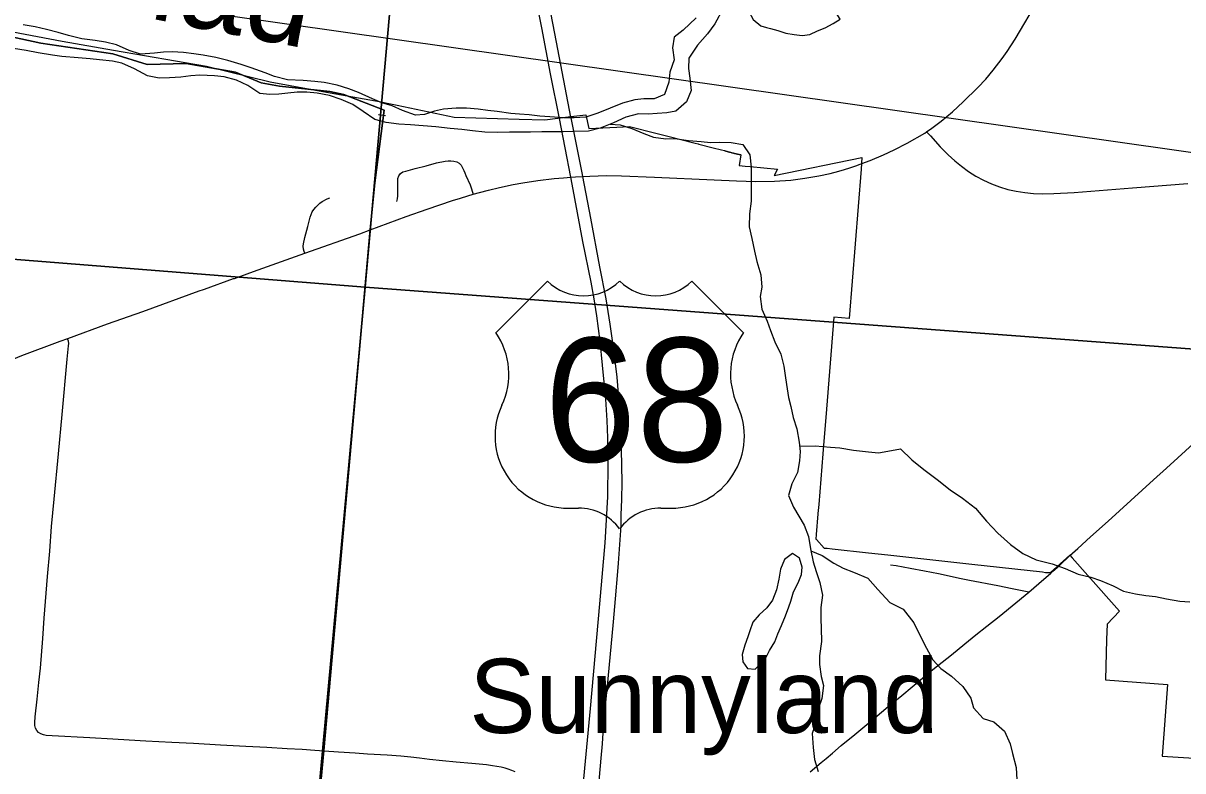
# Model space of a CAD drawing. Extents: x 0 to 34, y 0 to 22.
# Drawn here: x 6.536 to 7.77, y 18.205 to 19.001 of the extents above; entities that cross this region are included whole.
import ezdxf

# ---------------------------------------------------------------- set-up
doc = ezdxf.new("R2010")
doc.units = 0
for name, color, linetype in [('GM_X_Corporation', 7, 'Continuous'), ('GM_X_County_Road', 7, 'Continuous'), ('GM_X_Major_River', 7, 'Continuous'), ('GM_X_Major_River_Text', 7, 'Continuous'), ('GM_X_Minor_Lake', 7, 'Continuous'), ('GM_X_Minor_River', 7, 'Continuous'), ('GM_X_Township_Road', 7, 'Continuous'), ('GM_X_Unincorporated_Text', 7, 'Continuous'), ('GM_X_US_Location', 7, 'Continuous'), ('GM_X_US_Route', 7, 'Continuous'), ('GM_X_US_Shield', 7, 'Continuous'), ('SH_Text', 7, 'Continuous')]:
    doc.layers.add(name, color=color, linetype=linetype)

msp = doc.modelspace()

# ---------------------------------------------------------------- linework, layer by layer
at = {"layer": 'GM_X_Corporation'}
for points in [[(5.9917, 19.818), (6.9896, 19.7221), (6.9001, 18.7194), (5.8857, 18.8)], [(6.9896, 19.7221), (8.0005, 19.6268), (7.9102, 18.6438), (6.9001, 18.7194)], [(5.8857, 18.8), (6.9001, 18.7194), (6.8066, 17.7025), (5.8048, 17.783)]]:
    msp.add_lwpolyline(points, close=True, dxfattribs=at)
for points in [[(6.8137, 17.7739), (6.8245, 17.8909), (6.8563, 18.2261), (6.9053, 18.781), (6.9106, 18.8306), (6.9204, 18.908), (6.8775, 18.9245), (6.8626, 18.9279), (6.8089, 18.9336), (6.7895, 18.937), (6.762, 18.9484), (6.7095, 18.9576), (6.6683, 18.9564), (6.6317, 18.9678), (6.5552, 18.9793), (6.4809, 18.9953)], [(6.4809, 18.9953), (6.5552, 18.9793), (6.6317, 18.9678), (6.6683, 18.9564), (6.7095, 18.9576), (6.762, 18.9484), (6.7895, 18.937), (6.8089, 18.9336), (6.8626, 18.9279), (6.8775, 18.9245), (6.9204, 18.908), (6.9106, 18.8306), (6.9053, 18.781), (6.8563, 18.2261), (6.8245, 17.8909), (6.8137, 17.7739)], [(6.5121, 18.9937), (6.5779, 18.9815), (6.6325, 18.9717), (6.7314, 18.9547), (6.7991, 18.9381), (6.8628, 18.9265), (6.9171, 18.9167), (6.9219, 18.9157), (6.9342, 18.9131), (6.9948, 18.9004), (7.0641, 18.8984), (7.0913, 18.8976), (7.1189, 18.9011), (7.1351, 18.9031), (7.138, 18.8882), (7.1678, 18.8898), (7.1815, 18.8905), (7.2093, 18.8834), (7.2222, 18.8801), (7.2514, 18.8727), (7.2543, 18.872), (7.255, 18.8718), (7.2703, 18.8679), (7.2792, 18.8657), (7.2824, 18.8648), (7.2826, 18.8648), (7.2827, 18.8647), (7.2829, 18.8647), (7.2831, 18.8646), (7.2832, 18.8646), (7.2834, 18.8645), (7.2836, 18.8645), (7.2838, 18.8644), (7.2839, 18.8644), (7.2841, 18.8643), (7.2843, 18.8643), (7.2844, 18.8642), (7.2846, 18.8642), (7.2848, 18.8642), (7.2849, 18.8641), (7.2851, 18.8641), (7.2853, 18.864), (7.2855, 18.864), (7.2856, 18.8639), (7.2858, 18.8639), (7.286, 18.8638), (7.2861, 18.8638), (7.2863, 18.8637), (7.2865, 18.8637), (7.2866, 18.8636), (7.2868, 18.8636), (7.287, 18.8635), (7.2872, 18.8635), (7.2873, 18.8634), (7.2875, 18.8634), (7.2877, 18.8634), (7.2878, 18.8633), (7.288, 18.8633), (7.2881, 18.8632), (7.2882, 18.8632), (7.2884, 18.8632), (7.2885, 18.8631), (7.2887, 18.8631), (7.2889, 18.863), (7.289, 18.863), (7.2894, 18.8629), (7.2895, 18.8629), (7.2897, 18.8628), (7.2899, 18.8628), (7.2901, 18.8627), (7.2902, 18.8627), (7.2904, 18.8626), (7.2906, 18.8626), (7.2907, 18.8626), (7.2909, 18.8625), (7.2911, 18.8625), (7.2913, 18.8624), (7.2914, 18.8624), (7.2916, 18.8623), (7.2918, 18.8623), (7.2919, 18.8623), (7.2921, 18.8622), (7.2923, 18.8622), (7.2925, 18.8621), (7.2926, 18.8621), (7.2928, 18.862), (7.293, 18.862), (7.2932, 18.862), (7.2933, 18.8619), (7.2935, 18.8619), (7.2937, 18.8618), (7.2938, 18.8618), (7.2939, 18.8618), (7.294, 18.8618), (7.2942, 18.8617), (7.2944, 18.8617), (7.2945, 18.8616), (7.2947, 18.8616), (7.2949, 18.8616), (7.295, 18.8615), (7.2952, 18.8615), (7.2954, 18.8614), (7.2956, 18.8614), (7.2957, 18.8614), (7.2959, 18.8613), (7.2961, 18.8613), (7.2963, 18.8613), (7.2964, 18.8612), (7.2966, 18.8612), (7.2968, 18.8611), (7.2969, 18.8611), (7.2971, 18.8611), (7.2973, 18.861), (7.2975, 18.861), (7.2976, 18.861), (7.2978, 18.8609), (7.298, 18.8609), (7.2982, 18.8608), (7.2983, 18.8608), (7.2985, 18.8608), (7.2987, 18.8607), (7.2988, 18.8607), (7.299, 18.8607), (7.2992, 18.8606), (7.2994, 18.8606), (7.2995, 18.8606), (7.2997, 18.8605), (7.2982, 18.849), (7.3044, 18.8484), (7.3098, 18.8479), (7.3388, 18.8451), (7.3388, 18.8451), (7.3354, 18.8385), (7.4287, 18.8574), (7.4278, 18.845), (7.4153, 18.686), (7.3989, 18.6874), (7.3902, 18.5808), (7.3882, 18.5555), (7.3827, 18.488), (7.3819, 18.4785), (7.3819, 18.4783), (7.3801, 18.4563), (7.3797, 18.4513), (7.3802, 18.4507), (7.3887, 18.4417), (7.3919, 18.4414), (7.3971, 18.4408), (7.4356, 18.4366), (7.4564, 18.4343), (7.5264, 18.4266), (7.5457, 18.4244), (7.6209, 18.4162), (7.6241, 18.4158), (7.6294, 18.4155), (7.6499, 18.4342), (7.6524, 18.4314), (7.6691, 18.4125), (7.7027, 18.3745), (7.6896, 18.3605), (7.6891, 18.3445), (7.6878, 18.3014), (7.754, 18.2964), (7.748, 18.2201), (7.8666, 18.2127)], [(6.8132, 17.7739), (6.9001, 18.7194), (7.9102, 18.6438), (7.8167, 17.7739)]]:
    msp.add_lwpolyline(points, dxfattribs=at)
at = {"layer": 'GM_X_County_Road'}
for points in [[(7.4975, 18.8849), (7.5032, 18.8887), (7.5131, 18.8963), (7.525, 18.9062), (7.5365, 18.9167), (7.552, 18.9319), (7.5605, 18.941), (7.5685, 18.9505), (7.578, 18.9628), (7.5833, 18.9704), (7.5916, 18.9836), (7.6169, 19.0265)], [(7.4267, 18.8504), (7.4285, 18.851), (7.4374, 18.8543), (7.4517, 18.8603), (7.4629, 18.8655), (7.4767, 18.8728), (7.4956, 18.8835), (7.4975, 18.8849)], [(7.4975, 18.8849), (7.5015, 18.8805), (7.5119, 18.869), (7.5206, 18.8602), (7.5275, 18.8539), (7.5346, 18.8481), (7.5421, 18.8427), (7.5499, 18.8377), (7.5581, 18.8333), (7.5665, 18.8295), (7.5751, 18.8262), (7.584, 18.8235), (7.593, 18.8215), (7.6021, 18.8201), (7.6113, 18.8193), (7.6206, 18.8189), (7.633, 18.8191), (7.6546, 18.8204), (7.7166, 18.8252), (7.7755, 18.8298)], [(7.111, 18.8359), (7.1189, 18.8365), (7.1238, 18.8369), (7.1317, 18.8373), (7.1393, 18.8377), (7.1568, 18.8384), (7.173, 18.8381), (7.2081, 18.8366), (7.2716, 18.8336), (7.2951, 18.8325), (7.3157, 18.8319), (7.3358, 18.8322), (7.3529, 18.8334), (7.3679, 18.8354), (7.3829, 18.8379), (7.3948, 18.8405), (7.4043, 18.843), (7.4101, 18.8447), (7.4159, 18.8466), (7.4223, 18.8488), (7.4267, 18.8504)], [(7.0151, 18.8185), (7.0217, 18.8203), (7.0314, 18.8228), (7.043, 18.8256), (7.0577, 18.8287), (7.0679, 18.8304), (7.0839, 18.833), (7.1011, 18.8351), (7.111, 18.8359)], [(6.9055, 18.7805), (6.9439, 18.7947), (6.9661, 18.8024), (6.993, 18.8116), (7.0014, 18.8143), (7.0094, 18.8167), (7.0151, 18.8185)], [(6.8358, 18.7555), (6.8943, 18.7763), (6.9055, 18.7805)], [(6.7601, 18.7285), (6.7611, 18.7288), (6.7814, 18.7361), (6.8358, 18.7555)], [(6.7282, 18.7171), (6.7291, 18.7174), (6.7601, 18.7285)], [(6.5836, 18.6647), (6.6261, 18.6803), (6.6635, 18.6935), (6.7236, 18.7154), (6.7282, 18.7171)], [(6.2717, 18.5103), (6.3025, 18.5272), (6.3488, 18.5524), (6.3883, 18.5739), (6.4201, 18.591), (6.4474, 18.6058), (6.4777, 18.6217), (6.4917, 18.6285), (6.5117, 18.6372), (6.5348, 18.6466), (6.5755, 18.6618), (6.5836, 18.6647)], [(7.6319, 18.417), (7.6389, 18.4231), (7.6501, 18.4337), (7.6583, 18.4412), (7.672, 18.4538), (7.6906, 18.4704), (7.7388, 18.5142), (7.7527, 18.5267), (7.785, 18.5561), (7.8029, 18.5733), (7.821, 18.5904), (7.8357, 18.6041)], [(7.6063, 18.3948), (7.6168, 18.4039), (7.6296, 18.415), (7.6319, 18.417)], [(7.3906, 18.2178), (7.3973, 18.2234), (7.4067, 18.2314), (7.421, 18.2433), (7.4425, 18.261), (7.4568, 18.2729), (7.4712, 18.2847), (7.5042, 18.3123), (7.524, 18.3281), (7.5383, 18.3398), (7.5499, 18.3492), (7.5615, 18.3584), (7.5746, 18.3689), (7.6063, 18.3948)], [(7.3737, 18.2034), (7.3855, 18.2134), (7.3906, 18.2178)]]:
    msp.add_lwpolyline(points, dxfattribs=at)
at = {"layer": 'GM_X_Major_River'}
for points in [[(7.2809, 19.0162), (7.2721, 18.9997), (7.2643, 18.9893), (7.2538, 18.977), (7.2447, 18.9632), (7.2441, 18.9522), (7.2457, 18.9419), (7.2469, 18.9289), (7.2421, 18.9169), (7.2308, 18.9069), (7.2213, 18.9052), (7.211, 18.9043), (7.2012, 18.9038), (7.1909, 18.904), (7.1776, 18.9006), (7.1645, 18.8944), (7.1503, 18.8887), (7.1377, 18.8856), (7.121, 18.8852), (7.1108, 18.885), (7.0982, 18.885), (7.088, 18.8848), (7.0762, 18.8843), (7.0667, 18.8846), (7.0538, 18.8845), (7.0405, 18.884), (7.0273, 18.8844), (7.0144, 18.8858), (7.003, 18.8872), (6.9905, 18.8883), (6.9754, 18.8901), (6.9618, 18.8912), (6.9485, 18.8923), (6.936, 18.893), (6.9224, 18.8948), (6.9103, 18.8981), (6.898, 18.9064), (6.8871, 18.9138), (6.8747, 18.9194), (6.8623, 18.9235), (6.8491, 18.9261), (6.8381, 18.9271), (6.8279, 18.927), (6.818, 18.9261), (6.8081, 18.9248)], [(7.2522, 19.0063), (7.2386, 18.9929), (7.2289, 18.9856), (7.2271, 18.9742), (7.2291, 18.9616), (7.2242, 18.9484), (7.2232, 18.9378), (7.2187, 18.9247), (7.2076, 18.92), (7.1966, 18.9199), (7.1871, 18.9189), (7.1741, 18.9155), (7.1607, 18.9101), (7.1477, 18.9047), (7.135, 18.9004), (7.1225, 18.8996), (7.1115, 18.8998), (7.0967, 18.9009), (7.0861, 18.9016)], [(7.0861, 18.9016), (7.0748, 18.903), (7.0645, 18.9036), (7.0551, 18.9042), (7.0407, 18.9064), (7.0305, 18.9074), (7.0202, 18.9088), (7.0081, 18.9099), (6.9971, 18.9101), (6.9834, 18.9089), (6.9739, 18.9069), (6.9632, 18.9033), (6.9537, 18.9024), (6.9398, 18.9077), (6.9289, 18.9125), (6.9179, 18.9158), (6.9078, 18.9198), (6.8931, 18.9266), (6.8826, 18.9307), (6.8702, 18.9344), (6.8566, 18.9373), (6.8467, 18.9383), (6.8342, 18.9394), (6.8176, 18.9402), (6.8036, 18.9439), (6.7938, 18.9476), (6.7788, 18.9528), (6.7682, 18.9565), (6.7539, 18.9606), (6.7411, 18.964), (6.7278, 18.9666), (6.718, 18.9679), (6.7067, 18.9693), (6.6949, 18.97), (6.6854, 18.9698), (6.6759, 18.9686), (6.6611, 18.9674), (6.649, 18.9715), (6.6355, 18.9775), (6.6238, 18.9804), (6.6128, 18.9822), (6.5985, 18.984), (6.5845, 18.9874), (6.5736, 18.9907), (6.5611, 18.9937), (6.549, 18.9966), (6.5362, 18.9988)], [(6.8081, 18.9248), (6.7986, 18.9247), (6.788, 18.9257), (6.7753, 18.9343), (6.7633, 18.9399), (6.7501, 18.9433), (6.7399, 18.9446), (6.7243, 18.945), (6.7148, 18.9445), (6.7041, 18.9432), (6.692, 18.9424), (6.681, 18.9419), (6.6685, 18.9444), (6.6546, 18.952), (6.6411, 18.958), (6.6313, 18.9601), (6.6173, 18.9616), (6.6074, 18.9626), (6.5946, 18.9636), (6.5775, 18.9652), (6.5673, 18.9665), (6.5522, 18.9688), (6.5393, 18.9714), (6.5261, 18.9736)]]:
    msp.add_lwpolyline(points, dxfattribs=at)
at = {"layer": 'GM_X_Minor_Lake'}
for points in [[(7.3619, 19.0777), (7.3527, 19.0713), (7.3443, 19.0631), (7.3367, 19.0548), (7.3276, 19.0465), (7.3199, 19.0382), (7.3135, 19.0307), (7.3066, 19.022), (7.3084, 19.0129), (7.3129, 19.0045), (7.3211, 18.9976), (7.3271, 18.996)], [(7.3271, 18.996), (7.3313, 18.9949), (7.3393, 18.9926), (7.3479, 18.9898), (7.3566, 18.9883), (7.365, 18.9874), (7.3733, 18.9885), (7.3816, 18.9922), (7.3896, 18.9956), (7.398, 19.0001), (7.4056, 19.0046), (7.4007, 19.0126), (7.397, 19.0206), (7.3914, 19.0286), (7.3858, 19.037), (7.3798, 19.045), (7.3742, 19.0541), (7.3701, 19.0625), (7.3648, 19.0709), (7.3619, 19.0777)], [(7.3152, 18.3129), (7.3255, 18.3226), (7.3305, 18.3325), (7.3359, 18.3419), (7.3394, 18.3502), (7.3432, 18.3593), (7.3474, 18.3695), (7.3509, 18.379), (7.3532, 18.385), (7.356, 18.3952), (7.3609, 18.4047), (7.3644, 18.4134), (7.3652, 18.4213), (7.3623, 18.4308), (7.3547, 18.4358), (7.3491, 18.4315)], [(7.3491, 18.4315), (7.3464, 18.4294), (7.3421, 18.4192), (7.3402, 18.4086), (7.3378, 18.3972), (7.3336, 18.3863), (7.3275, 18.378), (7.3195, 18.3705), (7.3126, 18.3629), (7.3095, 18.3535), (7.3072, 18.347), (7.3041, 18.3383), (7.3014, 18.3285), (7.3021, 18.3205), (7.3069, 18.3133), (7.3152, 18.3129)]]:
    msp.add_lwpolyline(points, dxfattribs=at)
at = {"layer": 'GM_X_Minor_River'}
for points in [[(6.9217, 18.902), (6.9148, 18.9031), (6.9144, 18.9031)], [(7.1609, 18.8929), (7.1713, 18.8922), (7.1838, 18.8883), (7.1966, 18.8829), (7.2071, 18.879), (7.22, 18.8774), (7.2298, 18.8777), (7.2442, 18.8757), (7.2578, 18.8745), (7.2676, 18.8736), (7.2775, 18.8739), (7.2896, 18.8735), (7.302, 18.8715), (7.3095, 18.8604), (7.3109, 18.8471), (7.3108, 18.835), (7.3107, 18.8225), (7.311, 18.8111), (7.309, 18.7975), (7.3086, 18.7838), (7.3115, 18.7713), (7.3144, 18.7576), (7.317, 18.7466), (7.321, 18.7326), (7.3221, 18.7193), (7.3205, 18.7094), (7.3223, 18.6961), (7.3279, 18.6832), (7.3316, 18.6733), (7.336, 18.6612), (7.3423, 18.6482), (7.3457, 18.6353), (7.3471, 18.6254), (7.3485, 18.6159), (7.3507, 18.6019), (7.3529, 18.5924), (7.3555, 18.5806), (7.3595, 18.5685), (7.3621, 18.5544), (7.3631, 18.5446), (7.3623, 18.5347), (7.3603, 18.5222), (7.3542, 18.5101), (7.3507, 18.4976), (7.3559, 18.4851), (7.3615, 18.4756), (7.3671, 18.466), (7.3719, 18.4539), (7.3741, 18.441), (7.377, 18.4269), (7.38, 18.4167), (7.384, 18.4049), (7.3866, 18.3916), (7.385, 18.3783), (7.3849, 18.3662), (7.3855, 18.3559), (7.3858, 18.3423), (7.3834, 18.3271), (7.3834, 18.3177), (7.3852, 18.3048), (7.3877, 18.2953), (7.3861, 18.2816), (7.3823, 18.2703), (7.3795, 18.2551), (7.3756, 18.2442), (7.377, 18.2294), (7.3781, 18.2165), (7.3821, 18.2039)], [(7.3625, 18.5502), (7.3791, 18.5505), (7.3953, 18.5492), (7.4051, 18.5484), (7.4199, 18.546), (7.4358, 18.544), (7.4463, 18.5432), (7.46, 18.5457), (7.4698, 18.5472), (7.4818, 18.5357), (7.4946, 18.5254), (7.5089, 18.5147), (7.5225, 18.5036), (7.5356, 18.4948), (7.5496, 18.484), (7.5612, 18.4703), (7.5732, 18.4577), (7.5867, 18.4455), (7.5999, 18.4359), (7.6142, 18.429), (7.6312, 18.425), (7.6448, 18.42), (7.6587, 18.4138), (7.6723, 18.4107), (7.6825, 18.4072), (7.6961, 18.4014), (7.707, 18.3957), (7.7199, 18.3929), (7.7308, 18.3913), (7.741, 18.3901), (7.7527, 18.3877), (7.7671, 18.385), (7.7777, 18.3845)], [(7.3745, 18.4388), (7.3865, 18.4337), (7.3989, 18.4256), (7.4087, 18.4202), (7.4197, 18.416), (7.4351, 18.4098), (7.4456, 18.3976), (7.4584, 18.3838), (7.4727, 18.3765), (7.4839, 18.3621), (7.4899, 18.3495), (7.4974, 18.335), (7.5041, 18.3228), (7.5127, 18.3133), (7.524, 18.3053), (7.536, 18.2942), (7.5446, 18.282), (7.5476, 18.2717), (7.5577, 18.2603), (7.569, 18.2568), (7.5803, 18.2468), (7.5863, 18.2331), (7.5888, 18.2229), (7.5929, 18.2081), (7.5935, 18.1948)]]:
    msp.add_lwpolyline(points, dxfattribs=at)
at = {"layer": 'GM_X_Township_Road'}
for points in [[(6.9339, 18.8105), (6.9346, 18.8135), (6.9349, 18.8166), (6.935, 18.8197), (6.9348, 18.8321), (6.935, 18.8352), (6.9358, 18.8381), (6.9376, 18.8406), (6.9403, 18.8421), (6.9433, 18.843), (6.9532, 18.8457), (6.965, 18.8487), (6.9762, 18.8517), (6.9853, 18.8536), (6.9883, 18.8539), (6.9914, 18.8539), (6.9945, 18.8536), (6.9975, 18.8529), (7.0002, 18.8514), (7.0022, 18.8492), (7.0037, 18.8465), (7.005, 18.8438), (7.0062, 18.8411), (7.0074, 18.8383), (7.0117, 18.8283), (7.0133, 18.8242), (7.0141, 18.8218), (7.0151, 18.8185)], [(6.8358, 18.7555), (6.8353, 18.7573), (6.8347, 18.7598), (6.8343, 18.763), (6.8345, 18.7655), (6.836, 18.7724), (6.839, 18.7841), (6.8416, 18.794), (6.8426, 18.7969), (6.8439, 18.7997), (6.8455, 18.8022), (6.8475, 18.8046), (6.8496, 18.8068), (6.8518, 18.8088), (6.8543, 18.8106), (6.8596, 18.8135), (6.8624, 18.8147)], [(6.8565, 18.2256), (6.8466, 18.2263), (6.833, 18.2271), (6.817, 18.2281), (6.7956, 18.2293), (6.773, 18.2305), (6.7462, 18.232), (6.7174, 18.2336), (6.6944, 18.2348), (6.6667, 18.2362), (6.6492, 18.2373), (6.6316, 18.2384), (6.6073, 18.2398), (6.567, 18.2416), (6.5608, 18.2422), (6.5579, 18.2428), (6.5551, 18.2438), (6.5527, 18.2453), (6.5508, 18.2474), (6.5495, 18.2499), (6.5488, 18.2528), (6.5486, 18.2558), (6.5489, 18.2619), (6.5511, 18.2808), (6.553, 18.2985), (6.5546, 18.3137), (6.5572, 18.3454), (6.5587, 18.3671), (6.5622, 18.4113), (6.5645, 18.4383), (6.5665, 18.4645), (6.5692, 18.4938), (6.5737, 18.542), (6.5778, 18.5839), (6.583, 18.6427), (6.5846, 18.6569), (6.5847, 18.6594), (6.5843, 18.6618), (6.5839, 18.6639), (6.5836, 18.6647)], [(7.6063, 18.3948), (7.5885, 18.3984), (7.5734, 18.4013), (7.5433, 18.4073), (7.5342, 18.4091), (7.5102, 18.4141), (7.4952, 18.4171), (7.4801, 18.42), (7.465, 18.4228), (7.459, 18.4236)], [(7.0596, 18.2036), (7.0562, 18.205), (7.0524, 18.2064), (7.0492, 18.2073), (7.0449, 18.2083), (7.0402, 18.2092), (7.0356, 18.21), (7.0294, 18.2108), (7.0138, 18.2123), (6.9971, 18.2139), (6.9824, 18.2153), (6.9687, 18.2167), (6.958, 18.218), (6.9486, 18.2191), (6.9382, 18.22), (6.9236, 18.2211), (6.9025, 18.2223), (6.8894, 18.2232), (6.8718, 18.2244), (6.8565, 18.2256)]]:
    msp.add_lwpolyline(points, dxfattribs=at)
at = {"layer": 'GM_X_US_Route'}
for points in [[(7.1193, 18.8996), (7.1191, 18.9005), (7.1036, 18.9803), (7.0937, 19.032), (7.0841, 19.0807), (7.0753, 19.1264), (7.0657, 19.1751), (7.0544, 19.2329), (7.041, 19.2998), (7.0399, 19.3057)], [(7.1315, 18.1812), (7.1398, 18.2708), (7.1499, 18.3822), (7.1555, 18.4471), (7.1571, 18.4719), (7.1582, 18.4963), (7.1586, 18.5324), (7.1582, 18.5589), (7.1576, 18.5776), (7.1563, 18.6003), (7.1528, 18.6364), (7.1502, 18.6618), (7.1466, 18.6891), (7.1438, 18.7069), (7.1405, 18.7248), (7.1319, 18.7682), (7.1203, 18.8292), (7.1189, 18.8365), (7.1069, 18.899), (7.0975, 18.9465), (7.0881, 18.9954), (7.0802, 19.0351)], [(7.169, 18.4166), (7.1697, 18.4256), (7.1724, 18.4654), (7.1727, 18.4769), (7.1732, 18.4933), (7.1737, 18.5119), (7.173, 18.5467), (7.1719, 18.5742), (7.1704, 18.597), (7.1681, 18.6235), (7.1645, 18.6551), (7.161, 18.6799), (7.1564, 18.707), (7.15, 18.7412), (7.1402, 18.793), (7.1317, 18.8373), (7.131, 18.8412), (7.1193, 18.8996)], [(7.1044, 17.6994), (7.1073, 17.7311), (7.1081, 17.7395), (7.1115, 17.7788), (7.1152, 17.8179), (7.1176, 17.8462), (7.1206, 17.8779), (7.1227, 17.9021), (7.1247, 17.9238), (7.1278, 17.957), (7.1321, 18.0024), (7.1349, 18.0359), (7.1375, 18.0658), (7.1413, 18.1076), (7.1438, 18.1349), (7.1462, 18.1617), (7.1512, 18.2181), (7.1525, 18.2332), (7.1535, 18.2451), (7.1563, 18.2771), (7.1587, 18.3023), (7.1643, 18.3633), (7.1665, 18.3876), (7.169, 18.4166)]]:
    msp.add_lwpolyline(points, dxfattribs=at)
at = {"layer": 'GM_X_US_Shield'}
for p, q in [((7.094, 18.7259), (7.0391, 18.671)), ((7.3028, 18.671), (7.2479, 18.7259)), ((7.116, 18.4842), (7.127, 18.4842)), ((7.2149, 18.4842), (7.2259, 18.4842))]:
    msp.add_line(p, q, dxfattribs=at)
for centre, radius, start, end in [((7.1325, 18.7651), 0.0549, 225.573, 314.427), ((7.2094, 18.7651), 0.0549, 225.573, 314.427), ((6.9761, 18.6269), 0.0769, 334.5471, 35.0009), ((7.3658, 18.6269), 0.0769, 144.9991, 205.4529), ((7.1152, 18.5611), 0.0769, 154.8319, 270.6383), ((7.2267, 18.5611), 0.0769, 269.3617, 25.1681), ((7.127, 18.4293), 0.0549, 36.8699, 90), ((7.2149, 18.4293), 0.0549, 90, 143.1301)]:
    msp.add_arc(centre, radius, start, end, dxfattribs=at)
at = {"layer": 'SH_Text'}
msp.add_lwpolyline([(9.4769, 18.9817), (4.0338, 19.3956), (9.4769, 18.6217)], close=True, dxfattribs=at)

# ---------------------------------------------------------------- texts
at = {"layer": 'GM_X_Major_River_Text'}
msp.add_text('Mad', height=0.09469, rotation=349.0086, dxfattribs=at).set_placement((6.5943, 19.0205))
at = {"layer": 'GM_X_Unincorporated_Text'}
msp.add_text('Sunnyland', height=0.07898, rotation=0, dxfattribs=at).set_placement((7.011, 18.2448))
at = {"layer": 'GM_X_US_Location'}
for s in ['0', '/']:
    msp.add_text(s, height=0.000189, dxfattribs=at).set_placement((7.1709, 18.5985))
msp.add_text('68', height=0.000189, rotation=0, dxfattribs=at).set_placement((7.1318, 18.5593))
at = {"layer": 'GM_X_US_Shield'}
msp.add_text('68', height=0.13184, dxfattribs=at).set_placement((7.0907, 18.5336))

doc.saveas('drawing.dxf')
